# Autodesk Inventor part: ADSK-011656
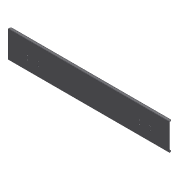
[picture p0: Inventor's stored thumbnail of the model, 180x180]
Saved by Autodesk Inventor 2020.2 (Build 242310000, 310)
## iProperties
Created: 2000-02
Part Number: ADSK-011656
Document SubType Name: Tôlerie
Description: FSHTPH,SS,CP,00,010,100,600,ADJUSTABLE SIDE PAN
Designer: sspink
Material: 1.0312 DC05
Density: 1 g/cm^3
Sheet Metal Rule: Stahlblech 1.0312 - DC05 -   1.5mm
Appearance: Metal-Steel(Polish)
Mass: 682.706 g
Surface Area: 9160.51 cm^2
Volume: 682.706 cm^3
Sheet Metal Width: 298,786 mm
Sheet Metal Length: 1524,000 mm
Sheet Metal Area: 455349,620 mm^2
Flat Pattern Width: 29.8786 cm
Flat Pattern Length: 152.4 cm
Flat Pattern Area: 4553.5 cm^2
Control State: 0
Checked Out: False
Master: False
Shininess: 57.0
Length Units: 11269
Angle Units: 11279
Time Units: 11290
Mass Units: 11283
Length Display Precision: 3
Angle Display Precision: 2
Compacted: True
Cutlength: 715 SI  (11.91 X 60.0)
Material Desc: SHEET,S/S,16 GAUGE
Material_Number: A084639
G_L: 298,8x1524 mm
Thickness: 1,500 mm
Dimensions: 254x25x1524 mm
Mass: 0,683 kg
Semi finished: Stahlblech 1.0312 - DC05 -   1.5mm
VLT_Material: 1.0312 DC05
Density: 8.03
Volumn: 731.1906235198854
Area: 9273.621438152142
PropertySet Name: Model Information
Author: sspink
Revision Number: -
Title: FSHTPH,SS,CP,00,010,100,600,ADJUSTABLE SIDE PAN
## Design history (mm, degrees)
node "Face1"
  sketch "Sketch1"
    geometry: L1 (-762, -127)-(762, -127); L2 (762, -127)-(762, 127); L3 (762, 127)-(-762, 127); L4 (-762, 127)-(-762, -127); 3 further points
    constraints: 8 end point, 2 midpoint, 2 parallel, 1 horizontal, 1 horizontal alignment, 1 perpendicular, 1 vertical alignment
    dimensions: "d0" = 254 distance between parallel lines of L3 L1; "d1" = 1524 distance between parallel lines of L2 L4
node "Lasche3"
node "Corner Round1" dims "d9" = 12.5
node "Hole1" dims "d14" = 9, "d15" = 9.525, "d16" = 6.35, "d17" = 60 deg, "d18" = 19.05, "d19" = 118 deg, "d41" = 6
  sketch "Sketch4"
    geometry: L1 (282, -124)-(182, -124); L2 (182, -124)-(182, -162); L3 (182, -162)-(282, -162); L4 (282, -162)-(282, -124); L5 (0, 0)-(0, -248) reference; 3 further points
    constraints: 8 end point, 2 parallel, 2 vertical alignment, 1 horizontal, 1 horizontal alignment, 1 midpoint, 1 perpendicular
    dimensions: "d38" = 100 distance of L1.start L1.end; "d39" = 38 distance of L3.end L1.start; "d40" = 182 distance between parallel lines of L5 L2
node "Mirror1"
node "Solide1"
node "Corps solides"
node "Corps surfaciques"
node "Plate1" dims "d27" = 1.5 (= Thickness)
sketch "Skizze5"
  geometry: L1 through (762, 0) direction (-1, 0); L2 through (0, -12.5) direction (0, -1); L3 (0, -25)-(1524, -25); L4 (1524, -25)-(1524, 0)
  constraints: 6 end point, 1 horizontal, 1 perpendicular, 1 vertical
feature "Grobblech4" dims "d27" = 1.5 (= Thickness), "d28" = 1.5 (= BendReliefWidth), "d29" = 0.75 (= BendReliefDepth), "d30" = 3 (= MinimumRemnant), "d31" = 1.5 (= TransitionRadius), "d32" = 25, "d33" = 90 deg, "d34" = 1.5 (= BendRadius), "d35" = 6 (= CornerReliefSize), "d36" = 1.5 (= TailleJeu), "d37" = 1.5 (= TailleRayonJacobi), "SeamGap" = 0.00508
feature "Biegung3" dims "d27" = 1.5 (= Thickness), "d28" = 1.5 (= BendReliefWidth), "d29" = 0.75 (= BendReliefDepth), "d30" = 3 (= MinimumRemnant), "d31" = 1.5 (= TransitionRadius), "d32" = 25, "d33" = 90 deg, "d34" = 1.5 (= BendRadius), "SeamGap" = 0.00508
feature "Ecke1" dims "d32" = 25, "d33" = 90 deg, "d35" = 6 (= CornerReliefSize), "d36" = 1.5 (= TailleJeu), "d37" = 1.5 (= TailleRayonJacobi)
feature "Definition1"
other parameters: "Thickness" = 1.5 (derived), "BendRadius" = 1.5 (= Thickness), "BendReliefWidth" = 1.5 (= Thickness), "BendReliefDepth" = 0.75 (= 0.5 x Thickness), "CornerReliefSize" = 6 (= 4 x Thickness), "MinimumRemnant" = 3 (= 2 x Thickness), "d2" = 1.5 (= BendRadius), "d3" = 25.4, "d4" = 90 deg, "d5" = 1.5 (= BendRadius), "TransitionRadius" = 1.5 (= BendRadius), "TailleRayonJacobi" = 1.5 (= BendRadius), "TailleJeu" = 1.5 (= Thickness), "BendRadius" = 1.5, "BendReliefDepth" = 0.75, "BendReliefWidth" = 1.5, "CornerReliefSize" = 6, "MinimumRemnant" = 3, "TailleJeu" = 1.5, "TailleRayonJacobi" = 1.5, "Thickness" = 1.5, "TransitionRadius" = 1.5
